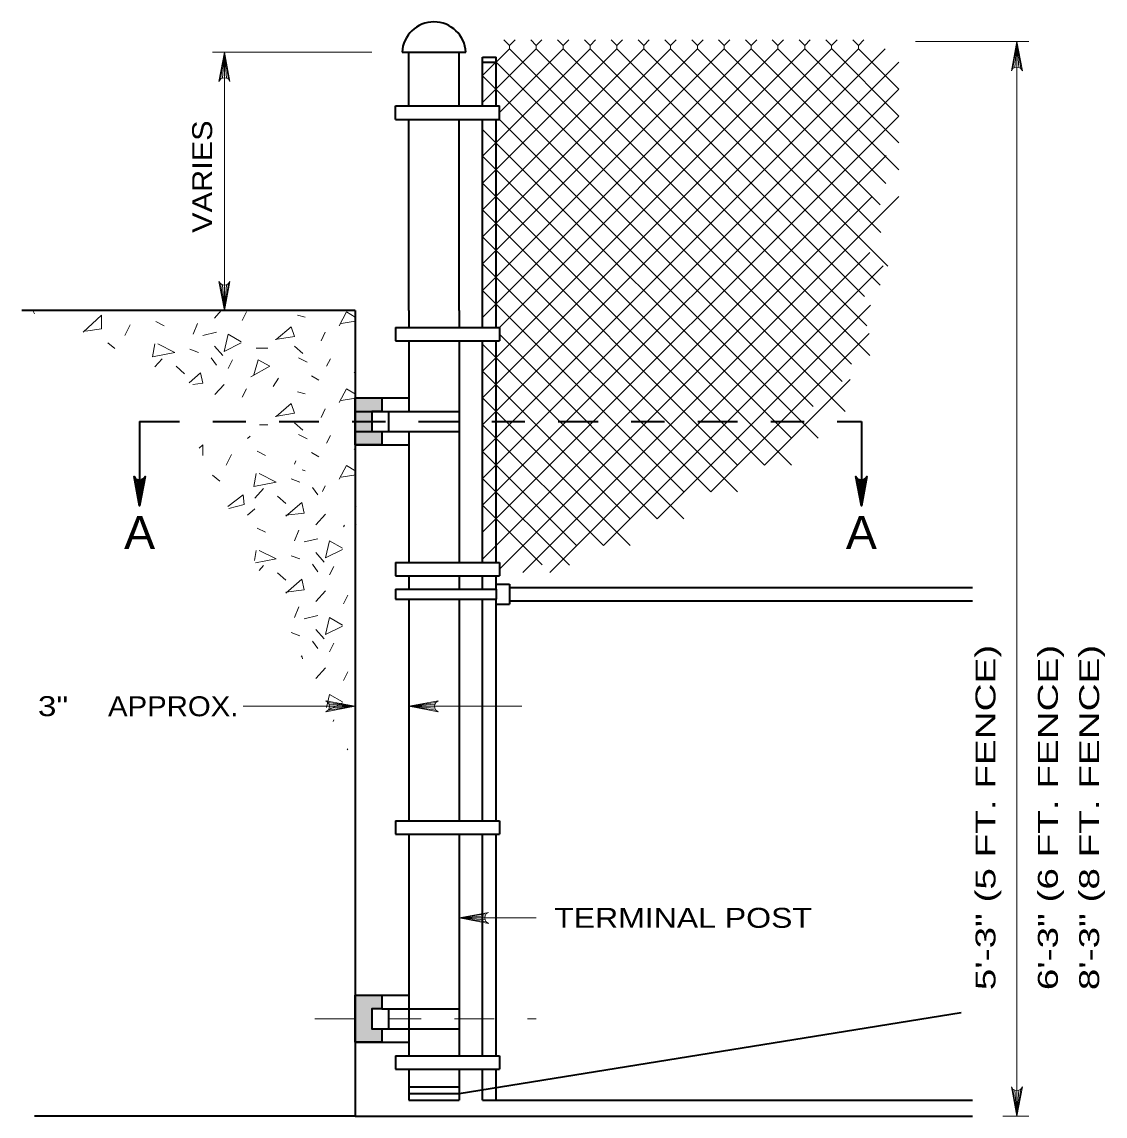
# Model space of a CAD drawing. Extents: x -29.89 to -22.78, y 99.65 to 109.34.
# Drawn here: x -29.574 to -26.313, y 102.481 to 105.774 of the extents above; entities that cross this region are included whole.
import ezdxf
from ezdxf.enums import TextEntityAlignment as Align

# ---------------------------------------------------------------- set-up
doc = ezdxf.new("R2010")
doc.units = 0
doc.header["$LTSCALE"] = 0.024
doc.linetypes.add('DOT_DASHED', pattern=[7.7, 5, -1.2, 0.3, -1.2])
for name, color, linetype, lineweight in [('1', 7, 'Continuous', 35), ('10', 7, 'Continuous', 13), ('12', 7, 'Continuous', 53), ('6', 7, 'Continuous', 13)]:
    doc.layers.add(name, color=color, linetype=linetype, lineweight=lineweight)

msp = doc.modelspace()

# ---------------------------------------------------------------- hatches: boundary and pattern name
at = {"layer": '1'}
for points in [[(-28.57106, 104.64233), (-28.49025, 104.64233), (-28.49025, 104.60194), (-28.52054, 104.60194), (-28.52054, 104.54133), (-28.49025, 104.54133), (-28.49025, 104.50092), (-28.57106, 104.50092)], [(-28.57106, 102.84435), (-28.49025, 102.84435), (-28.49025, 102.80396), (-28.52054, 102.80396), (-28.52054, 102.74335), (-28.49025, 102.74335), (-28.49025, 102.70294), (-28.57106, 102.70294)]]:
    msp.add_hatch(color=256, dxfattribs=at).paths.add_polyline_path(points)

# ---------------------------------------------------------------- linework, layer by layer
for p, q in [((-28.42965, 105.68275), (-28.23773, 105.68275)), ((-28.40944, 105.52112), (-28.40944, 105.68275)), ((-28.25792, 105.52112), (-28.25792, 105.68275)), ((-28.18721, 105.52112), (-28.18721, 105.66758)), ((-28.18721, 105.66758), (-28.14681, 105.66758)), ((-28.18721, 105.65244), (-28.14681, 105.65244)), ((-28.14681, 105.52112), (-28.14681, 105.66758)), ((-28.44983, 105.52112), (-28.13671, 105.52112)), ((-28.44983, 105.48073), (-28.44983, 105.52112)), ((-28.13671, 105.48073), (-28.13671, 105.52112)), ((-28.44983, 105.48073), (-28.13671, 105.48073)), ((-28.40944, 104.90496), (-28.40944, 105.48073)), ((-28.25792, 104.90496), (-28.25792, 105.48073)), ((-28.18721, 104.85446), (-28.18721, 105.48073)), ((-28.14681, 104.85446), (-28.14681, 105.48073)), ((-28.57106, 104.90496), (-29.57404, 104.90496)), ((-28.57106, 104.90496), (-28.57106, 102.48073)), ((-28.40944, 104.90496), (-28.40944, 104.85446)), ((-28.25792, 104.90496), (-28.25792, 104.85446)), ((-28.44983, 104.85446), (-28.13671, 104.85446)), ((-28.44983, 104.85446), (-28.44983, 104.81406)), ((-28.13671, 104.85446), (-28.13671, 104.81406)), ((-28.44983, 104.81406), (-28.13671, 104.81406)), ((-28.40944, 104.81406), (-28.40944, 104.60194)), ((-28.25792, 104.81406), (-28.25792, 104.1474)), ((-28.18721, 104.1474), (-28.18721, 104.81406)), ((-28.14681, 104.1474), (-28.14681, 104.81406)), ((-28.57106, 104.64233), (-28.40944, 104.64233)), ((-28.49025, 104.64233), (-28.49025, 104.60194)), ((-28.57106, 104.60194), (-28.25792, 104.60194)), ((-28.52054, 104.60194), (-28.52054, 104.54133)), ((-28.47004, 104.60194), (-28.47004, 104.54133)), ((-28.57106, 104.54133), (-28.25792, 104.54133)), ((-28.49025, 104.54133), (-28.49025, 104.50092)), ((-28.40944, 104.54133), (-28.40944, 104.1474)), ((-28.57106, 104.50092), (-28.40944, 104.50092)), ((-28.44983, 104.1474), (-28.13671, 104.1474)), ((-28.44983, 104.1474), (-28.44983, 104.10698)), ((-28.13671, 104.1474), (-28.13671, 104.10698)), ((-28.44983, 104.10698), (-28.13671, 104.10698)), ((-28.40944, 104.10698), (-28.40944, 104.06658)), ((-28.25792, 104.10698), (-28.25792, 104.06658)), ((-28.18721, 104.06658), (-28.18721, 104.10698)), ((-28.14681, 104.06658), (-28.14681, 104.10698)), ((-28.14681, 104.08173), (-28.1064, 104.08173)), ((-28.1064, 104.08173), (-28.1064, 104.02112)), ((-28.1064, 104.07162), (-28.02275, 104.07162)), ((-28.44983, 104.06658), (-28.44983, 104.03627)), ((-28.44983, 104.06658), (-28.14681, 104.06658)), ((-28.14681, 104.06658), (-28.14681, 104.03627)), ((-28.44983, 104.03627), (-28.14681, 104.03627)), ((-28.40944, 104.03627), (-28.40944, 103.3696)), ((-28.25792, 104.03627), (-28.25792, 103.3696)), ((-28.18721, 103.3696), (-28.18721, 104.03627)), ((-28.14681, 103.3696), (-28.14681, 104.03627)), ((-28.14681, 104.02112), (-28.1064, 104.02112)), ((-28.1064, 104.03123), (-28.04062, 104.03123)), ((-28.44983, 103.3696), (-28.13671, 103.3696)), ((-28.44983, 103.3696), (-28.44983, 103.32921)), ((-28.13671, 103.3696), (-28.13671, 103.32921)), ((-28.44983, 103.32921), (-28.13671, 103.32921)), ((-28.40944, 103.32921), (-28.40944, 102.66254)), ((-28.25792, 103.32921), (-28.25792, 102.66254)), ((-28.18721, 102.66254), (-28.18721, 103.32921)), ((-28.14681, 102.66254), (-28.14681, 103.32921)), ((-28.57106, 102.84435), (-28.40944, 102.84435)), ((-28.49025, 102.84435), (-28.49025, 102.80396)), ((-28.52054, 102.80396), (-28.52054, 102.74335)), ((-28.49025, 102.80396), (-28.25792, 102.80396)), ((-28.47004, 102.80396), (-28.47004, 102.74335)), ((-28.25792, 102.54892), (-26.74706, 102.79277)), ((-28.49025, 102.74335), (-28.25792, 102.74335)), ((-28.49025, 102.74335), (-28.49025, 102.70294)), ((-28.57106, 102.70294), (-28.40944, 102.70294)), ((-28.44983, 102.66254), (-28.13671, 102.66254)), ((-28.44983, 102.66254), (-28.44983, 102.62212)), ((-28.13671, 102.66254), (-28.13671, 102.62212)), ((-28.44983, 102.62212), (-28.13671, 102.62212)), ((-28.40944, 102.62212), (-28.40944, 102.52871)), ((-28.25792, 102.62212), (-28.25792, 102.52871)), ((-28.18721, 102.52871), (-28.18721, 102.62212)), ((-28.14681, 102.52871), (-28.14681, 102.62212)), ((-28.40944, 102.5691), (-28.25792, 102.5691)), ((-28.40944, 102.54892), (-28.25792, 102.54892)), ((-28.40944, 102.52871), (-28.25792, 102.52871)), ((-28.18721, 102.52871), (-27.8451, 102.52871)), ((-28.57106, 102.48073), (-29.53654, 102.48073)), ((-28.57106, 102.48073), (-26.71246, 102.48073))]:
    msp.add_line(p, q, dxfattribs=at)
for points in [[(-28.57106, 104.64233), (-28.49025, 104.64233), (-28.49025, 104.60194), (-28.52054, 104.60194), (-28.52054, 104.54133), (-28.49025, 104.54133), (-28.49025, 104.50092), (-28.57106, 104.50092)], [(-28.57106, 102.84435), (-28.49025, 102.84435), (-28.49025, 102.80396), (-28.52054, 102.80396), (-28.52054, 102.74335), (-28.49025, 102.74335), (-28.49025, 102.70294), (-28.57106, 102.70294)]]:
    msp.add_lwpolyline(points, close=True, dxfattribs=at)
for points in [[(-28.1064, 104.07162), (-27.40944, 104.07162), (-26.71246, 104.07162)], [(-28.1064, 104.03123), (-27.40944, 104.03123), (-26.71246, 104.03123)], [(-28.14681, 102.52871), (-27.44983, 102.52871), (-26.71246, 102.52871)]]:
    msp.add_lwpolyline(points, dxfattribs=at)
msp.add_arc((-28.33368, 105.67805), 0.09607, 2.79735, 177.20265, dxfattribs=at)
at = {"layer": '10'}
for p, q in [((-26.88448, 105.71502), (-26.54279, 105.71502)), ((-26.57915, 105.71502), (-26.57915, 102.48073)), ((-28.52054, 105.68275), (-29.00071, 105.68275)), ((-28.96433, 105.68275), (-28.96433, 104.90496)), ((-28.57106, 103.71423), (-28.90808, 103.71423)), ((-28.06965, 103.71423), (-28.40944, 103.71423)), ((-28.25792, 103.0775), (-28.02652, 103.0775)), ((-26.62156, 102.48073), (-26.54279, 102.48073))]:
    msp.add_line(p, q, dxfattribs=at)
at = {"layer": '10', "linetype": 'DOT_DASHED', "lineweight": 35}
msp.add_line((-29.21973, 104.57162), (-27.04715, 104.57162), dxfattribs=at)
at = {"layer": '10', "lineweight": 35}
for p, q in [((-29.21973, 104.57162), (-29.21973, 104.31767)), ((-27.04715, 104.57162), (-27.04715, 104.31767))]:
    msp.add_line(p, q, dxfattribs=at)
at = {"layer": '10', "linetype": 'DOT_DASHED'}
msp.add_line((-28.69227, 102.77365), (-28.0256, 102.77365), dxfattribs=at)
at = {"layer": '10'}
for points in [[(-26.57915, 105.71502), (-26.5626, 105.62675), (-26.56731, 105.63356), (-26.57323, 105.63706), (-26.57915, 105.63808), (-26.58506, 105.63706), (-26.59098, 105.63356), (-26.59571, 105.62675), (-26.57915, 105.71502), (-26.59098, 105.63356), (-26.58506, 105.63706), (-26.57915, 105.71502), (-26.57915, 105.63808), (-26.57323, 105.63706), (-26.57915, 105.71502), (-26.56731, 105.63356)], [(-28.96433, 105.68275), (-28.94779, 105.59448), (-28.9525, 105.60127), (-28.95842, 105.60479), (-28.96433, 105.60579), (-28.97025, 105.60479), (-28.97617, 105.60127), (-28.9809, 105.59448), (-28.96433, 105.68275), (-28.97617, 105.60127), (-28.97025, 105.60479), (-28.96433, 105.68275), (-28.96433, 105.60579), (-28.95842, 105.60479), (-28.96433, 105.68275), (-28.9525, 105.60127)], [(-28.96433, 104.90496), (-28.9809, 104.99323), (-28.97617, 104.98642), (-28.97025, 104.98292), (-28.96433, 104.9819), (-28.95842, 104.98292), (-28.9525, 104.98642), (-28.94779, 104.99323), (-28.96433, 104.90496), (-28.9525, 104.98642), (-28.95842, 104.98292), (-28.96433, 104.90496), (-28.96433, 104.9819), (-28.97025, 104.98292), (-28.96433, 104.90496), (-28.97617, 104.98642)], [(-28.57106, 103.71423), (-28.65931, 103.69769), (-28.65252, 103.7024), (-28.649, 103.70831), (-28.648, 103.71423), (-28.649, 103.72015), (-28.65252, 103.72606), (-28.65931, 103.73079), (-28.57106, 103.71423), (-28.65252, 103.72606), (-28.649, 103.72015), (-28.57106, 103.71423), (-28.648, 103.71423), (-28.649, 103.70831), (-28.57106, 103.71423), (-28.65252, 103.7024)], [(-28.40944, 103.71423), (-28.32117, 103.73079), (-28.32798, 103.72606), (-28.33148, 103.72015), (-28.3325, 103.71423), (-28.33148, 103.70831), (-28.32798, 103.7024), (-28.32117, 103.69769), (-28.40944, 103.71423), (-28.32798, 103.7024), (-28.33148, 103.70831), (-28.40944, 103.71423), (-28.3325, 103.71423), (-28.33148, 103.72015), (-28.40944, 103.71423), (-28.32798, 103.72606)], [(-28.25792, 103.0775), (-28.16967, 103.09404), (-28.17646, 103.08933), (-28.17996, 103.08342), (-28.18098, 103.0775), (-28.17996, 103.07158), (-28.17646, 103.06567), (-28.16967, 103.06094), (-28.25792, 103.0775), (-28.17646, 103.06567), (-28.17996, 103.07158), (-28.25792, 103.0775), (-28.18098, 103.0775), (-28.17996, 103.08342), (-28.25792, 103.0775), (-28.17646, 103.08933)], [(-26.57915, 102.48073), (-26.59571, 102.56898), (-26.59098, 102.56219), (-26.58506, 102.55867), (-26.57915, 102.55767), (-26.57323, 102.55867), (-26.56731, 102.56219), (-26.5626, 102.56898), (-26.57915, 102.48073), (-26.56731, 102.56219), (-26.57323, 102.55867), (-26.57915, 102.48073), (-26.57915, 102.55767), (-26.58506, 102.55867), (-26.57915, 102.48073), (-26.59098, 102.56219)]]:
    msp.add_lwpolyline(points, dxfattribs=at)
at = {"layer": '10', "lineweight": 35}
for points in [[(-29.21973, 104.31767), (-29.23627, 104.40592), (-29.23156, 104.39912), (-29.22565, 104.39562), (-29.21973, 104.3946), (-29.21381, 104.39562), (-29.2079, 104.39912), (-29.20319, 104.40592), (-29.21973, 104.31767), (-29.2079, 104.39912), (-29.21381, 104.39562), (-29.21973, 104.31767), (-29.21973, 104.3946), (-29.22565, 104.39562), (-29.21973, 104.31767), (-29.23156, 104.39912)], [(-27.04715, 104.31767), (-27.06369, 104.40592), (-27.05898, 104.39912), (-27.05306, 104.39562), (-27.04715, 104.3946), (-27.04123, 104.39562), (-27.03531, 104.39912), (-27.0306, 104.40592), (-27.04715, 104.31767), (-27.03531, 104.39912), (-27.04123, 104.39562), (-27.04715, 104.31767), (-27.04715, 104.3946), (-27.05306, 104.39562), (-27.04715, 104.31767), (-27.05898, 104.39912)]]:
    msp.add_lwpolyline(points, dxfattribs=at)
at = {"layer": '6'}
for p, q in [((-28.08919, 105.7199), (-28.10612, 105.70296)), ((-28.00867, 105.72017), (-28.0256, 105.70325)), ((-27.92785, 105.72017), (-27.94479, 105.70325)), ((-27.84706, 105.72017), (-27.86398, 105.70325)), ((-27.76625, 105.72017), (-27.78317, 105.70325)), ((-27.68544, 105.72017), (-27.70237, 105.70325)), ((-27.60462, 105.72017), (-27.62156, 105.70325)), ((-27.52381, 105.72017), (-27.54075, 105.70325)), ((-27.44302, 105.72017), (-27.45994, 105.70325)), ((-27.36221, 105.72017), (-27.37912, 105.70325)), ((-27.2814, 105.72017), (-27.29833, 105.70325)), ((-27.20087, 105.7199), (-27.21781, 105.70296)), ((-27.12006, 105.7199), (-27.137, 105.70296)), ((-27.03927, 105.7199), (-27.05619, 105.70296)), ((-27.37912, 105.69283), (-28.18721, 104.88477)), ((-27.45994, 105.69283), (-28.18721, 104.96556)), ((-27.54075, 105.69283), (-28.18721, 105.04637)), ((-27.62156, 105.69283), (-28.18721, 105.12719)), ((-27.70237, 105.69283), (-28.18721, 105.208)), ((-27.78317, 105.69283), (-28.18721, 105.28879)), ((-28.18721, 105.3696), (-27.86398, 105.69283)), ((-28.0256, 105.69283), (-28.18721, 105.53123)), ((-27.05619, 105.69254), (-28.18721, 104.56152)), ((-27.137, 105.69254), (-28.18721, 104.64233)), ((-26.97537, 105.69254), (-28.18721, 104.48073)), ((-27.21781, 105.69254), (-28.18721, 104.72315)), ((-28.10612, 105.69254), (-28.18721, 105.6126)), ((-27.29833, 105.69283), (-28.13671, 104.85446)), ((-27.94479, 105.69283), (-28.13671, 105.50092)), ((-28.10612, 105.70296), (-28.10612, 105.69254)), ((-28.10612, 105.69254), (-27.10542, 104.69185)), ((-28.0256, 105.70325), (-28.0256, 105.69283)), ((-28.0256, 105.69283), (-27.07658, 104.74381)), ((-27.94479, 105.70325), (-27.94479, 105.69283)), ((-27.94479, 105.69283), (-27.02181, 104.76985)), ((-27.86398, 105.70325), (-27.86398, 105.69283)), ((-27.86398, 105.69283), (-27.03054, 104.8594)), ((-27.78317, 105.70325), (-27.78317, 105.69283)), ((-27.78317, 105.69283), (-27.03806, 104.94773)), ((-27.70237, 105.70325), (-27.70237, 105.69283)), ((-27.70237, 105.69283), (-26.991, 104.98148)), ((-27.62156, 105.70325), (-27.62156, 105.69283)), ((-27.62156, 105.69283), (-26.96717, 105.03846)), ((-27.54075, 105.70325), (-27.54075, 105.69283)), ((-27.54075, 105.69283), (-26.98829, 105.1404)), ((-27.45994, 105.70325), (-27.45994, 105.69283)), ((-27.45994, 105.69283), (-26.99048, 105.2234)), ((-27.37912, 105.70325), (-27.37912, 105.69283)), ((-27.37912, 105.69283), (-26.97375, 105.28746)), ((-27.29833, 105.70325), (-27.29833, 105.69283)), ((-27.29833, 105.69283), (-26.93469, 105.32921)), ((-27.21781, 105.70296), (-27.21781, 105.69254)), ((-27.21723, 105.69254), (-26.93469, 105.41002)), ((-27.137, 105.70296), (-27.137, 105.69254)), ((-27.13642, 105.69254), (-26.93469, 105.49081)), ((-27.05619, 105.70296), (-27.05619, 105.69254)), ((-27.0556, 105.69254), (-26.93469, 105.57162)), ((-26.93469, 105.65244), (-28.18721, 104.39992)), ((-28.14681, 105.65244), (-27.09631, 104.60194)), ((-28.18721, 105.61204), (-27.19177, 104.61658)), ((-26.93469, 105.57162), (-28.18721, 104.3191)), ((-26.93469, 105.49081), (-28.18721, 104.23829)), ((-28.13671, 105.48073), (-27.1771, 104.52112)), ((-28.18721, 105.45042), (-27.25792, 104.52112)), ((-26.9726, 105.3721), (-28.18721, 104.15748)), ((-28.18721, 105.3696), (-27.25792, 104.44031)), ((-28.18721, 105.28879), (-27.33873, 104.44031)), ((-27.01502, 105.24887), (-28.13671, 104.12719)), ((-26.93469, 105.2484), (-28.066, 104.11708)), ((-28.18721, 105.208), (-27.41954, 104.44031)), ((-28.18721, 105.12719), (-27.41954, 104.3595)), ((-27.02177, 105.0805), (-27.98519, 104.11708)), ((-27.50035, 104.3595), (-28.18721, 105.04637)), ((-26.98137, 105.04008), (-27.82358, 104.1979)), ((-27.58115, 104.3595), (-28.18721, 104.96556)), ((-29.53571, 104.8959), (-29.54075, 104.90496)), ((-29.45625, 104.90496), (-29.45658, 104.90446)), ((-28.97379, 104.90496), (-28.99446, 104.882)), ((-28.89819, 104.90125), (-28.91102, 104.87558)), ((-27.0194, 104.92127), (-27.66196, 104.27871)), ((-29.26404, 104.83067), (-29.24798, 104.86275)), ((-29.17096, 104.87237), (-29.14529, 104.85954)), ((-29.04581, 104.86596), (-29.05865, 104.83387)), ((-28.74415, 104.89162), (-28.72169, 104.88521)), ((-28.5709, 104.8729), (-28.61256, 104.86596)), ((-28.98804, 104.84029), (-29.02977, 104.83067)), ((-28.67354, 104.8146), (-28.66071, 104.84029)), ((-28.13671, 104.83425), (-27.58115, 104.27871)), ((-27.02333, 104.83652), (-27.50035, 104.3595)), ((-29.31537, 104.80819), (-29.29408, 104.79117)), ((-28.99446, 104.79856), (-28.96879, 104.76969)), ((-28.75377, 104.79856), (-28.7281, 104.7761)), ((-28.18721, 104.80396), (-27.66196, 104.27871)), ((-29.06827, 104.78894), (-29.0426, 104.77931)), ((-29.00408, 104.76327), (-28.98804, 104.74079)), ((-28.86931, 104.79215), (-28.834, 104.79215)), ((-28.74094, 104.76327), (-28.71527, 104.75044)), ((-28.57044, 104.77669), (-28.57085, 104.7761)), ((-29.1735, 104.73552), (-29.15171, 104.76006)), ((-29.11, 104.73758), (-29.08431, 104.71513)), ((-28.9399, 104.75685), (-28.95275, 104.73117)), ((-28.6575, 104.73758), (-28.64467, 104.76006)), ((-28.81796, 104.67663), (-28.80192, 104.70229)), ((-28.70242, 104.70871), (-28.67996, 104.69588)), ((-28.57017, 104.72135), (-28.57406, 104.71833)), ((-28.18721, 104.72315), (-27.74277, 104.27871)), ((-27.08119, 104.69785), (-27.33873, 104.44031)), ((-28.96558, 104.68304), (-28.99321, 104.65233)), ((-28.89819, 104.67019), (-28.91102, 104.64452)), ((-28.74415, 104.66056), (-28.72169, 104.65415)), ((-28.56979, 104.64202), (-28.61256, 104.6349)), ((-27.74277, 104.1979), (-28.18721, 104.64233)), ((-28.67354, 104.58354), (-28.66071, 104.60923)), ((-28.75377, 104.5675), (-28.7281, 104.54504)), ((-28.8589, 104.56108), (-28.834, 104.56108)), ((-28.56933, 104.54721), (-28.57085, 104.54504)), ((-28.18721, 104.56152), (-27.82358, 104.1979)), ((-28.89485, 104.52027), (-28.88658, 104.52735)), ((-28.74094, 104.53221), (-28.71527, 104.51937)), ((-28.6575, 104.50652), (-28.64467, 104.529)), ((-28.95904, 104.44006), (-28.943, 104.47215)), ((-28.86598, 104.48177), (-28.84029, 104.46894)), ((-28.70242, 104.47765), (-28.67996, 104.46481)), ((-28.56906, 104.49117), (-28.57406, 104.48727)), ((-28.18721, 104.48073), (-27.9044, 104.1979)), ((-28.7499, 104.45265), (-28.75365, 104.44327)), ((-29.00033, 104.40954), (-28.97829, 104.39192)), ((-28.73081, 104.42571), (-28.72169, 104.42308)), ((-28.56869, 104.41115), (-28.61256, 104.40383)), ((-28.8724, 104.34056), (-28.84671, 104.36946)), ((-28.76327, 104.39833), (-28.7376, 104.38871)), ((-28.69908, 104.37267), (-28.68304, 104.35019)), ((-28.6694, 104.36079), (-28.66071, 104.37817)), ((-28.18721, 104.39992), (-27.926, 104.13869)), ((-28.805, 104.34698), (-28.77931, 104.32452)), ((-28.89485, 104.28923), (-28.8724, 104.30848)), ((-28.56823, 104.31773), (-28.57085, 104.31398)), ((-28.18721, 104.3191), (-28.00844, 104.14033)), ((-28.66058, 104.29244), (-28.68946, 104.26033)), ((-28.86598, 104.25071), (-28.84029, 104.23788)), ((-28.74081, 104.24429), (-28.75365, 104.21221)), ((-28.60306, 104.25983), (-28.60602, 104.25392)), ((-28.56796, 104.26096), (-28.57198, 104.25783)), ((-28.68304, 104.21863), (-28.72477, 104.209)), ((-28.86919, 104.18331), (-28.87431, 104.15252)), ((-28.68946, 104.1769), (-28.66379, 104.14802)), ((-28.86004, 104.1234), (-28.84671, 104.1384)), ((-28.76327, 104.16727), (-28.7376, 104.15765)), ((-28.69908, 104.1416), (-28.68304, 104.11912)), ((-28.805, 104.11592), (-28.77931, 104.09346)), ((-28.63492, 104.13519), (-28.64775, 104.1095)), ((-28.66058, 104.06137), (-28.68946, 104.02927)), ((-28.59319, 104.04854), (-28.60602, 104.02285)), ((-28.74081, 104.01323), (-28.75365, 103.98115)), ((-28.68304, 103.98756), (-28.72477, 103.97794)), ((-28.68946, 103.94583), (-28.66379, 103.91696)), ((-28.76327, 103.93621), (-28.7376, 103.92658)), ((-28.69908, 103.91054), (-28.68304, 103.88808)), ((-28.63492, 103.90412), (-28.64775, 103.87844)), ((-28.66058, 103.83031), (-28.68946, 103.79821)), ((-28.59319, 103.81748), (-28.60602, 103.79179)), ((-28.60923, 103.7244), (-28.65356, 103.70225)), ((-28.63492, 103.67306), (-28.6371, 103.66869)), ((-28.59319, 103.58642), (-28.595, 103.58281))]:
    msp.add_line(p, q, dxfattribs=at)
for points in [[(-28.12304, 105.7199), (-28.10612, 105.70296), (-28.10612, 105.69742)], [(-28.04252, 105.72017), (-28.0256, 105.70325), (-28.0256, 105.69771)], [(-27.96171, 105.72017), (-27.94479, 105.70325), (-27.94479, 105.69771)], [(-27.88092, 105.72017), (-27.86398, 105.70325), (-27.86398, 105.69771)], [(-27.8001, 105.72017), (-27.78317, 105.70325), (-27.78317, 105.69771)], [(-27.71929, 105.72017), (-27.70237, 105.70325), (-27.70237, 105.69771)], [(-27.63848, 105.72017), (-27.62156, 105.70325), (-27.62156, 105.69771)], [(-27.55767, 105.72017), (-27.54075, 105.70325), (-27.54075, 105.69771)], [(-27.47687, 105.72017), (-27.45994, 105.70325), (-27.45994, 105.69771)], [(-27.39606, 105.72017), (-27.37912, 105.70325), (-27.37912, 105.69771)], [(-27.31525, 105.72017), (-27.29833, 105.70325), (-27.29833, 105.69771)], [(-27.23473, 105.7199), (-27.21781, 105.70296), (-27.21781, 105.69742)], [(-27.15394, 105.7199), (-27.137, 105.70296), (-27.137, 105.69742)], [(-27.07312, 105.7199), (-27.05619, 105.70296), (-27.05619, 105.69742)], [(-28.61898, 104.85954), (-28.59652, 104.90125), (-28.57096, 104.88552)], [(-29.38277, 104.8435), (-29.33462, 104.84992), (-29.33462, 104.89162), (-29.38919, 104.84029)], [(-28.91423, 104.80819), (-28.96558, 104.78252), (-28.95275, 104.83387), (-28.91423, 104.8114)], [(-28.81154, 104.81781), (-28.75377, 104.82744), (-28.7634, 104.85633), (-28.80833, 104.81781)], [(-29.17417, 104.80498), (-29.18058, 104.76648), (-29.11321, 104.77931), (-29.16454, 104.80498)], [(-28.88535, 104.7055), (-28.82758, 104.73758), (-28.86287, 104.75685), (-28.87573, 104.71192)], [(-29.05919, 104.68279), (-29.02977, 104.68625), (-29.03619, 104.71833), (-29.07094, 104.68821)], [(-28.61898, 104.62848), (-28.59652, 104.67019), (-28.56985, 104.65377)], [(-28.81154, 104.58675), (-28.75377, 104.5964), (-28.7634, 104.62527), (-28.80833, 104.58675)], [(-29.02965, 104.46931), (-29.02965, 104.50102), (-29.04027, 104.49102)], [(-28.61898, 104.39742), (-28.59652, 104.43915), (-28.56873, 104.42204)], [(-28.86919, 104.41437), (-28.8756, 104.37587), (-28.80821, 104.38871), (-28.85954, 104.41437)], [(-28.95106, 104.30906), (-28.90448, 104.32131), (-28.90769, 104.35019), (-28.95415, 104.31535)], [(-28.77931, 104.28923), (-28.72477, 104.29565), (-28.73119, 104.32773), (-28.77931, 104.28602)], [(-28.60923, 104.18652), (-28.66058, 104.16085), (-28.64775, 104.21221), (-28.60923, 104.18973)], [(-28.87096, 104.14569), (-28.80821, 104.15765), (-28.85954, 104.18331)], [(-28.77931, 104.05817), (-28.72477, 104.06458), (-28.73119, 104.09667), (-28.77931, 104.05496)], [(-28.60923, 103.95546), (-28.66058, 103.92979), (-28.64775, 103.98115), (-28.60923, 103.95867)], [(-28.72948, 103.85712), (-28.73119, 103.8656), (-28.73292, 103.8641)], [(-28.65762, 103.71056), (-28.64775, 103.75008), (-28.60923, 103.72763)]]:
    msp.add_lwpolyline(points, dxfattribs=at)

# ---------------------------------------------------------------- texts
at = {"layer": '12'}
for s, width, p in [('VARIES', 1.15, (-29.0014, 105.30832)), ('5\'-3" (5 FT. FENCE)', 1.45, (-26.64356, 103.37954)), ('6\'-3" (6 FT. FENCE)', 1.45, (-26.45572, 103.37954)), ('8\'-3" (8 FT. FENCE)', 1.45, (-26.33152, 103.37954))]:
    msp.add_text(s, height=0.06, rotation=90, dxfattribs=dict(at, width=width)).set_placement(p, align=Align.CENTER)
for s, height, width, p in [('A', 0.1, 1.05, (-29.21971, 104.18735)), ('A', 0.1, 1.05, (-27.04714, 104.18735)), ('3"', 0.06, 1.25, (-29.48024, 103.68464))]:
    msp.add_text(s, height=height, dxfattribs=dict(at, width=width)).set_placement(p, align=Align.CENTER)
at = {"layer": '12', "width": 1.1}
msp.add_text('APPROX.', height=0.06, dxfattribs=at).set_placement((-28.92237, 103.68423), align=Align.RIGHT)
at = {"layer": '12', "width": 1.2}
msp.add_text('TERMINAL POST', height=0.06, dxfattribs=at).set_placement((-27.97166, 103.04749))

doc.saveas('drawing.dxf')
